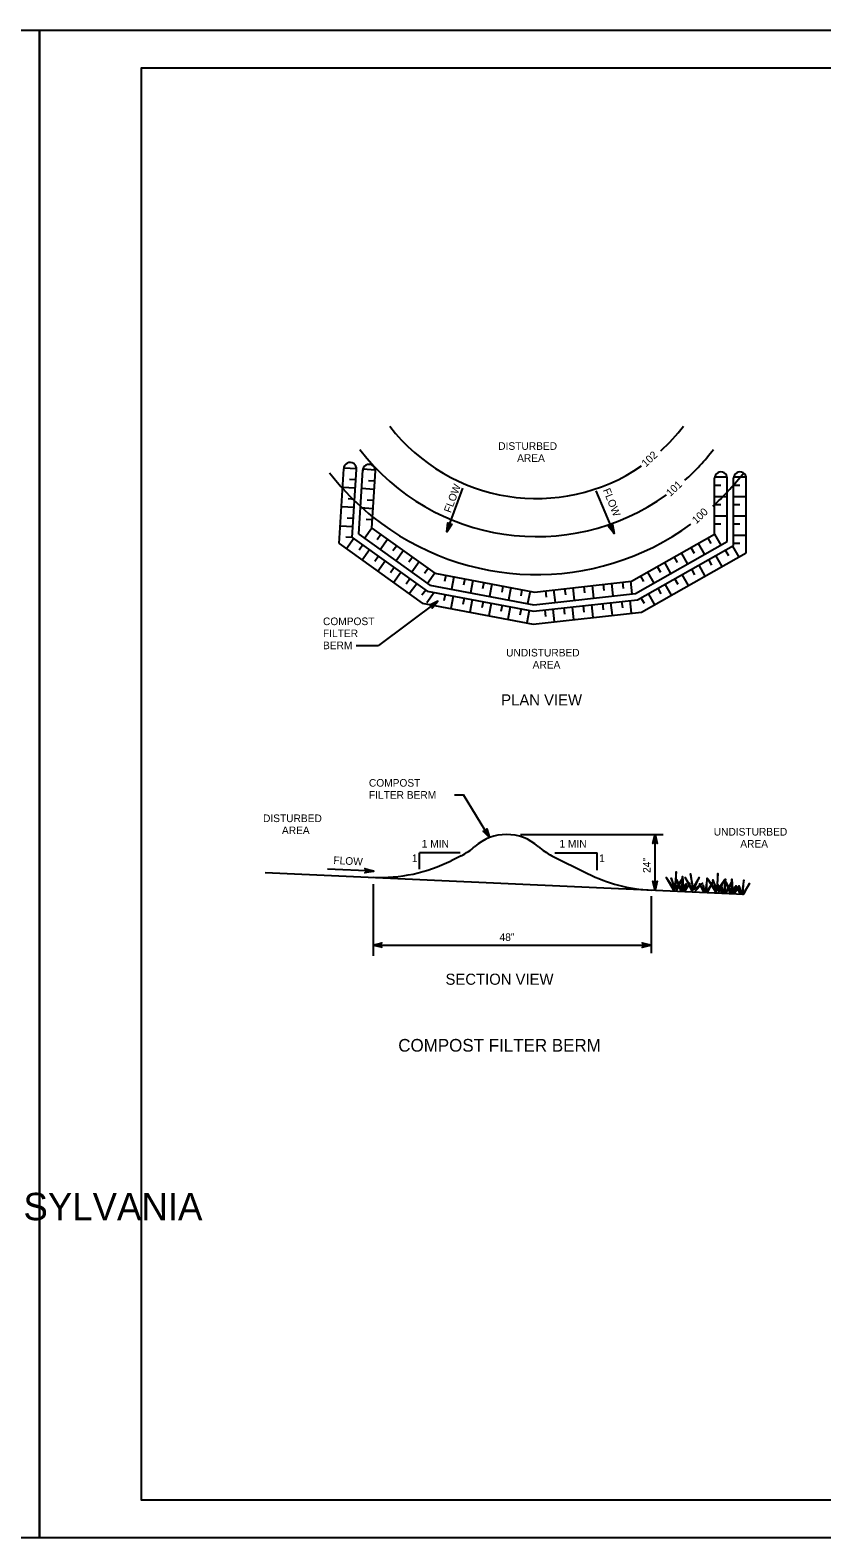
# Model space of a CAD drawing. Extents: x 636462 to 639049, y 299944 to 300538.
# Drawn here: x 638140 to 638452, y 299944 to 300538 of the extents above; entities that cross this region are included whole.
import ezdxf

# ---------------------------------------------------------------- set-up
doc = ezdxf.new("R2010")
doc.units = 0
for name, color, linetype in [('1', 7, 'Continuous'), ('Default', 7, 'Continuous'), ('PLT-BNDY', 7, 'Continuous')]:
    doc.layers.add(name, color=color, linetype=linetype)

msp = doc.modelspace()

# ---------------------------------------------------------------- linework, layer by layer
at = {"layer": '1'}
msp.add_lwpolyline([(638969.91, 299959.45), (638969.91, 300523.45), (638183.91, 300523.45), (638183.91, 299959.45), (638969.91, 299959.45), (638969.91, 299985.81), (638769.91, 299985.81), (638769.91, 300050.49), (638969.91, 300050.49), (638969.91, 300079.45), (638769.91, 300079.45), (638769.91, 299959.45), (638848.72, 299959.45), (638848.72, 299985.81), (638848.72, 299959.45), (638925.72, 299959.45), (638925.72, 299985.81), (638925.72, 299973.49), (638969.91, 299973.49)], dxfattribs=at)
at = {"layer": 'Default'}
for p, q in [((638261.94, 300336.14), (638263.75, 300365.65)), ((638268.75, 300365.59), (638263.76, 300365.89)), ((638267.09, 300338.59), (638268.74, 300365.34)), ((638269.71, 300339.83), (638271.26, 300365.19)), ((638276.27, 300365.13), (638271.28, 300365.43)), ((638274.86, 300342.28), (638276.25, 300364.88)), ((638409.85, 300362.41), (638414.85, 300362.41)), ((638417.38, 300362.41), (638422.38, 300362.41)), ((638268.28, 300357.97), (638263.3, 300358.28)), ((638268.48, 300361.22), (638265.99, 300361.37)), ((638275.8, 300357.51), (638270.81, 300357.82)), ((638276, 300360.76), (638273.51, 300360.91)), ((638304.37, 300340.79), (638310.66, 300357.94)), ((638370.27, 300340.08), (638363.16, 300356.9)), ((638409.85, 300339.85), (638409.85, 300361.89)), ((638409.85, 300359.16), (638412.35, 300359.16)), ((638414.85, 300336.93), (638414.85, 300361.89)), ((638417.38, 300335.45), (638417.38, 300361.89)), ((638417.38, 300359.16), (638419.88, 300359.16)), ((638422.38, 300332.53), (638422.38, 300361.89)), ((638267.82, 300350.36), (638262.83, 300350.66)), ((638268.01, 300353.6), (638265.52, 300353.76)), ((638275.33, 300349.9), (638270.34, 300350.2)), ((638275.53, 300353.14), (638273.04, 300353.3)), ((638409.85, 300354.78), (638414.85, 300354.78)), ((638409.85, 300351.53), (638412.35, 300351.53)), ((638417.38, 300354.78), (638422.38, 300354.78)), ((638417.38, 300351.53), (638419.88, 300351.53)), ((638267.55, 300345.99), (638265.05, 300346.14)), ((638275.06, 300345.53), (638272.57, 300345.68)), ((638409.85, 300347.15), (638414.85, 300347.15)), ((638417.38, 300347.15), (638422.38, 300347.15)), ((638267.35, 300342.74), (638262.36, 300343.05)), ((638267.09, 300338.59), (638264.6, 300338.74)), ((638274.86, 300342.28), (638271.95, 300338.22)), ((638278.42, 300339.73), (638276.97, 300337.7)), ((638407.22, 300338.36), (638408.44, 300336.19)), ((638409.85, 300343.9), (638412.35, 300343.9)), ((638409.85, 300339.85), (638412.31, 300335.5)), ((638417.38, 300343.9), (638419.88, 300343.9)), ((638417.38, 300339.52), (638422.38, 300339.52)), ((638267.69, 300338.16), (638264.78, 300334.1)), ((638271.25, 300335.61), (638269.79, 300333.58)), ((638273.89, 300333.71), (638270.98, 300329.65)), ((638281.06, 300337.83), (638278.15, 300333.77)), ((638284.62, 300335.28), (638283.16, 300333.25)), ((638287.26, 300333.39), (638284.35, 300329.33)), ((638396.76, 300332.46), (638399.21, 300328.11)), ((638400.57, 300334.61), (638401.8, 300332.44)), ((638403.4, 300336.21), (638405.86, 300331.86)), ((638414.09, 300333.59), (638415.32, 300331.42)), ((638416.92, 300335.19), (638419.38, 300330.84)), ((638417.38, 300336.27), (638419.88, 300336.27)), ((638277.45, 300331.16), (638275.99, 300329.13)), ((638280.09, 300329.26), (638277.18, 300325.2)), ((638283.65, 300326.71), (638282.19, 300324.68)), ((638290.82, 300330.84), (638289.36, 300328.81)), ((638293.46, 300328.94), (638290.55, 300324.88)), ((638387.28, 300327.12), (638388.51, 300324.94)), ((638390.11, 300328.71), (638392.57, 300324.36)), ((638393.93, 300330.86), (638395.15, 300328.69)), ((638403.63, 300327.69), (638406.09, 300323.34)), ((638407.44, 300329.84), (638408.67, 300327.67)), ((638410.28, 300331.44), (638412.73, 300327.09)), ((638286.29, 300324.82), (638283.38, 300320.76)), ((638289.85, 300322.27), (638288.39, 300320.24)), ((638297.02, 300326.39), (638295.56, 300324.36)), ((638299.66, 300324.49), (638296.75, 300320.43)), ((638303.96, 300323.68), (638303.5, 300321.23)), ((638307.16, 300323.08), (638306.23, 300318.17)), ((638311.46, 300322.27), (638311, 300319.81)), ((638314.66, 300321.66), (638313.73, 300316.75)), ((638318.96, 300320.85), (638318.49, 300318.4)), ((638369.2, 300320.49), (638369.76, 300315.53)), ((638373.55, 300320.98), (638373.83, 300318.5)), ((638376.78, 300321.34), (638377.34, 300316.37)), ((638380.64, 300323.37), (638381.86, 300321.19)), ((638383.47, 300324.96), (638385.92, 300320.61)), ((638394.15, 300322.35), (638395.38, 300320.17)), ((638396.99, 300323.94), (638399.44, 300319.59)), ((638400.8, 300326.09), (638402.03, 300323.92)), ((638292.49, 300320.37), (638289.58, 300316.31)), ((638296.05, 300317.82), (638294.59, 300315.79)), ((638299.38, 300316.88), (638296.47, 300312.82)), ((638303.68, 300316.07), (638303.22, 300313.62)), ((638306.87, 300315.47), (638305.95, 300310.56)), ((638311.18, 300314.66), (638310.71, 300312.2)), ((638322.15, 300320.25), (638321.23, 300315.34)), ((638326.46, 300319.44), (638325.99, 300316.98)), ((638329.65, 300318.83), (638328.72, 300313.92)), ((638333.95, 300318.02), (638333.49, 300315.57)), ((638337.15, 300317.42), (638336.22, 300312.51)), ((638343.22, 300317.58), (638343.5, 300315.1)), ((638346.45, 300317.94), (638347.01, 300312.98)), ((638350.8, 300318.43), (638351.08, 300315.95)), ((638354.04, 300318.79), (638354.59, 300313.83)), ((638358.39, 300319.28), (638358.66, 300316.8)), ((638361.62, 300319.64), (638362.18, 300314.68)), ((638365.97, 300320.13), (638366.25, 300317.65)), ((638380.86, 300314.85), (638382.09, 300312.67)), ((638383.7, 300316.45), (638386.15, 300312.09)), ((638387.51, 300318.6), (638388.74, 300316.42)), ((638390.34, 300320.19), (638392.8, 300315.84)), ((638300.88, 300313.48), (638277.41, 300296.05)), ((638314.37, 300314.05), (638313.44, 300309.14)), ((638318.67, 300313.24), (638318.21, 300310.79)), ((638321.87, 300312.64), (638320.94, 300307.73)), ((638326.17, 300311.83), (638325.71, 300309.37)), ((638329.37, 300311.22), (638328.44, 300306.31)), ((638333.67, 300310.41), (638333.2, 300307.96)), ((638336.86, 300309.81), (638335.94, 300304.9)), ((638342.94, 300309.97), (638343.22, 300307.49)), ((638346.17, 300310.33), (638346.73, 300305.37)), ((638350.52, 300310.82), (638350.8, 300308.34)), ((638353.75, 300311.18), (638354.31, 300306.22)), ((638358.1, 300311.67), (638358.38, 300309.19)), ((638361.33, 300312.03), (638361.89, 300307.07)), ((638365.68, 300312.52), (638365.96, 300310.04)), ((638368.92, 300312.88), (638369.47, 300307.92)), ((638373.27, 300313.37), (638373.54, 300310.89)), ((638376.5, 300313.73), (638377.05, 300308.76)), ((638268.67, 300296.05), (638277.41, 300296.05)), ((638307.41, 300237.15), (638310.91, 300237.15)), ((638321.24, 300220.33), (638310.91, 300237.15)), ((638333.39, 300221.55), (638389.59, 300221.55)), ((638386.42, 300199.66), (638386.42, 300221.55)), ((638386.68, 300221.55), (638388.17, 300221.55)), ((638309.6, 300214.33), (638293.61, 300214.33)), ((638293.61, 300207.94), (638293.61, 300214.33)), ((638346.95, 300214.33), (638363.58, 300214.33)), ((638363.58, 300207.56), (638363.58, 300214.33)), ((638275.55, 300207.1), (638257.3, 300207.93)), ((638310.07, 300213.2), (638306.09, 300211.22)), ((638345.77, 300213.2), (638359.81, 300206.19)), ((638275.3, 300201.97), (638275.3, 300173.78)), ((638384.88, 300197.24), (638384.88, 300174.75))]:
    msp.add_line(p, q, dxfattribs=at)
for points in [[(638306.07, 300343.62), (638306.37, 300343.8), (638304.37, 300340.79), (638306.07, 300343.62), (638305.65, 300343.56), (638304.37, 300340.79), (638305.15, 300343.73), (638304.86, 300344.03), (638304.37, 300340.79), (638304.72, 300344.38), (638304.86, 300344.03)], [(638267.09, 300338.59), (638296.63, 300317.4), (638338.59, 300309.48), (638379.47, 300314.06), (638417.38, 300335.45)], [(638269.71, 300339.83), (638297.65, 300319.79), (638338.68, 300312.04), (638378.68, 300316.52), (638414.85, 300336.93)], [(638274.86, 300342.28), (638299.66, 300324.49), (638338.87, 300317.09), (638377.11, 300321.38), (638409.85, 300339.85)], [(638369.6, 300343.3), (638369.7, 300343.64), (638370.27, 300340.08), (638369.6, 300343.3), (638369.34, 300342.98), (638370.27, 300340.08), (638368.86, 300342.77), (638368.44, 300342.79), (638370.27, 300340.08), (638368.1, 300342.95), (638368.44, 300342.79)], [(638261.94, 300336.14), (638294.61, 300312.7), (638338.4, 300304.43), (638381.04, 300309.21), (638422.38, 300332.53)], [(638297.92, 300312.03), (638297.57, 300312.05), (638300.88, 300313.48), (638297.92, 300312.03), (638298.3, 300311.86), (638300.88, 300313.48), (638298.62, 300311.44), (638298.7, 300311.03), (638300.88, 300313.48), (638298.63, 300310.66), (638298.7, 300311.03)], [(638320.08, 300223.41), (638320.13, 300223.76), (638321.24, 300220.33), (638320.08, 300223.41), (638319.87, 300223.05), (638321.24, 300220.33), (638319.43, 300222.77), (638319.01, 300222.72), (638321.24, 300220.33), (638318.65, 300222.83), (638319.01, 300222.72)], [(638385.78, 300218.32), (638385.56, 300218.05), (638386.42, 300221.55), (638385.78, 300218.32), (638386.15, 300218.51), (638386.42, 300221.55), (638386.68, 300218.52), (638387.05, 300218.34), (638386.42, 300221.55), (638387.31, 300218.05), (638387.05, 300218.34)], [(638272.37, 300207.95), (638272.12, 300208.19), (638275.55, 300207.1), (638272.37, 300207.95), (638272.54, 300207.57), (638275.55, 300207.1), (638272.51, 300207.04), (638272.3, 300206.68), (638275.55, 300207.1), (638272, 300206.45), (638272.3, 300206.68)], [(638232.84, 300206.64), (638421.46, 300197.98)], [(638387.06, 300202.89), (638387.28, 300203.16), (638386.42, 300199.66), (638387.06, 300202.89), (638386.68, 300202.7), (638386.42, 300199.66), (638386.16, 300202.69), (638385.78, 300202.87), (638386.42, 300199.66), (638385.53, 300203.15), (638385.78, 300202.87)], [(638394.94, 300199.19), (638397.4, 300204.47), (638394.61, 300200.23), (638394.73, 300206.86), (638394.26, 300200.77), (638392.71, 300204.35), (638394.22, 300199.9), (638390.76, 300204.59), (638393.99, 300199.24)], [(638396.69, 300199.26), (638394.88, 300203.87), (638397.06, 300199.31), (638397.29, 300204.96), (638397.58, 300199.31), (638398.66, 300202.1), (638397.82, 300199.35), (638400.1, 300202.4), (638398.07, 300199.15)], [(638401.95, 300198.88), (638405.11, 300202.42), (638401.72, 300199.94), (638403.82, 300204.59), (638401.42, 300200.52), (638400.39, 300206.04), (638401.3, 300199.66), (638398.31, 300204.65), (638401, 300199.02)], [(638407.07, 300198.72), (638409.27, 300203), (638406.64, 300198.68), (638406.99, 300204.32), (638406.12, 300198.74), (638405.34, 300201.63), (638405.89, 300198.8), (638403.93, 300202.06), (638405.55, 300198.78)], [(638411.41, 300198.53), (638413.87, 300203.81), (638411.08, 300199.58), (638411.2, 300206.21), (638410.72, 300200.12), (638409.18, 300203.69), (638410.69, 300199.25), (638407.23, 300203.93), (638410.45, 300198.59)], [(638414.33, 300198.32), (638416.53, 300202.61), (638413.9, 300198.29), (638414.25, 300203.93), (638413.38, 300198.34), (638412.59, 300201.23), (638413.15, 300198.41), (638411.19, 300201.67), (638412.8, 300198.38)], [(638416.14, 300198.23), (638414.32, 300202.85), (638416.5, 300198.28), (638416.73, 300203.93), (638417.03, 300198.28), (638418.1, 300201.08), (638417.27, 300198.32), (638419.55, 300201.36), (638417.51, 300198.11)], [(638421.46, 300197.99), (638423.66, 300202.27), (638421.03, 300197.95), (638421.38, 300203.59), (638420.5, 300198), (638419.72, 300200.89), (638420.27, 300198.07), (638418.31, 300201.33), (638419.93, 300198.04)], [(638278.53, 300177.35), (638278.8, 300177.13), (638275.3, 300178), (638278.53, 300177.35), (638278.33, 300177.73), (638275.3, 300178), (638278.33, 300178.25), (638278.51, 300178.62), (638275.3, 300178), (638278.79, 300178.88), (638278.51, 300178.62)], [(638275.3, 300178), (638384.88, 300178)], [(638381.64, 300178.6), (638381.37, 300178.82), (638384.88, 300178), (638381.64, 300178.6), (638381.84, 300178.23), (638384.88, 300178), (638381.85, 300177.7), (638381.67, 300177.33), (638384.88, 300178), (638381.39, 300177.07), (638381.67, 300177.33)]]:
    msp.add_lwpolyline(points, dxfattribs=at)
for centre, radius, start, end in [((638339.76, 300426.98), 73.04, 217.62146, 304.47323), ((638339.76, 300426.98), 73.04, 312.03677, 322.37854), ((638266.25, 300365.65), 2.5, 352.9854, 180.00062), ((638339.76, 300426.98), 88.03, 217.62146, 305.53768), ((638339.76, 300426.98), 88.03, 311.56592, 322.37854), ((638339.76, 300426.98), 103.02, 217.62146, 222.06503), ((638273.75, 300364.88), 2.5, 359.99938, 180.00062), ((638412.35, 300361.89), 2.5, 359.99938, 180.00062), ((638339.76, 300426.98), 103.02, 312.87336, 322.37854), ((638419.88, 300361.89), 2.5, 359.99938, 180.00062), ((638339.76, 300426.98), 103.02, 222.06503, 231.15361), ((638339.76, 300426.98), 103.02, 312.41473, 312.87336), ((638339.76, 300426.98), 103.02, 231.15361, 306.13463), ((638327.92, 300202.68), 18.87, 90, 131.4478), ((638327.92, 300202.68), 18.87, 48.5522, 90), ((638298.89, 300235.55), 24.98, 296.56505, 311.4478), ((638356.95, 300235.55), 24.98, 228.5522, 243.43495), ((638278.16, 300267.08), 62.46, 267.37187, 296.56505), ((638387.74, 300262.05), 62.46, 243.43495, 267.37187)]:
    msp.add_arc(centre, radius, start, end, dxfattribs=at)
at = {"layer": 'PLT-BNDY'}
for points in [[(637302.91, 300538.45), (638143.91, 300538.45), (638143.91, 299944.45), (637302.91, 299944.45)], [(638143.91, 300538.45), (638984.91, 300538.45), (638984.91, 299944.45), (638143.91, 299944.45)]]:
    msp.add_lwpolyline(points, close=True, dxfattribs=at)

# ---------------------------------------------------------------- texts
at = {"layer": '1'}
msp.add_text('COMMONWEALTH OF PENNSYLVANIA', height=10.7834, dxfattribs=at).set_placement((637942.07, 300069.59))
at = {"layer": 'Default'}
for s, height, p in [('DISTURBED', 2.998, (638324.64, 300373.1)), ('AREA', 2.998, (638332.08, 300368.36)), ('COMPOST', 2.998, (638255.58, 300304.04)), ('FILTER', 2.998, (638255.58, 300299.3)), ('BERM', 2.998, (638255.58, 300294.55)), ('UNDISTURBED', 2.998, (638327.74, 300291.69)), ('AREA', 2.998, (638338.19, 300286.94)), ('PLAN VIEW', 4.372, (638325.81, 300272.4)), ('COMPOST', 2.998, (638273.68, 300240.4)), ('FILTER BERM', 2.998, (638273.68, 300235.65)), ('DISTURBED', 2.998, (638231.95, 300226.44)), ('AREA', 2.998, (638239.4, 300221.69)), ('UNDISTURBED', 2.998, (638409.56, 300221.13)), ('1', 3, (638290.61, 300210.69)), ('1 MIN', 2.998, (638294.48, 300216.43)), ('1 MIN', 2.998, (638348.74, 300216.43)), ('1', 3, (638364.39, 300210.69)), ('AREA', 2.998, (638420.01, 300216.38)), ('48"', 2.998, (638325.15, 300179.61)), ('SECTION VIEW', 4.3721, (638303.86, 300162.35)), ('COMPOST FILTER BERM', 4.9967, (638285.24, 300136))]:
    msp.add_text(s, height=height, dxfattribs=at).set_placement(p)
for s, rotation, p in [('102', 43.15239, (638382.8, 300366.13)), ('FLOW', 69.55071, (638305.92, 300348.06)), ('FLOW', 291.98244, (638365.82, 300357.26)), ('101', 43.15239, (638392.46, 300354.51)), ('100', 43.15239, (638402.67, 300343.74)), ('FLOW', 357.06624, (638259.63, 300209.94)), ('24"', 90, (638384.66, 300206.42))]:
    msp.add_text(s, height=2.998, rotation=rotation, dxfattribs=at).set_placement(p)

doc.saveas('drawing.dxf')
